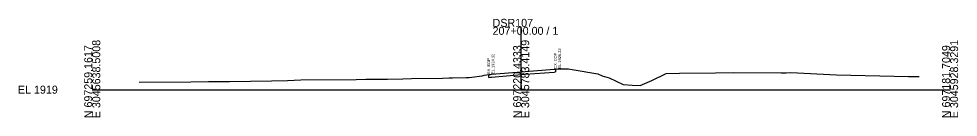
# Model space of a CAD drawing. Extents: x -26 to 19003, y -31 to 24541.
# Drawn here: x 1974.3 to 2302.8, y 17490.3 to 17524.9 of the extents above; entities that cross this region are included whole.
import ezdxf

# ---------------------------------------------------------------- set-up
doc = ezdxf.new("R2010")
doc.units = 0
for name, color, linetype in [('DESIGN - SHEET - Light Grid', 7, 'Continuous'), ('SURVEY - GROUND - Existing Pavement Layer', 7, 'Continuous'), ('SURVEY - GROUND - Existing Pavement Text', 7, 'Continuous'), ('SURVEY - GROUND - Top of Ground', 7, 'Continuous')]:
    doc.layers.add(name, color=color, linetype=linetype)

msp = doc.modelspace()

# ---------------------------------------------------------------- linework, layer by layer
at = {"layer": 'DESIGN - SHEET - Light Grid'}
for p, q in [((2150, 17500), (2150, 17522.06)), ((2000, 17500), (2150, 17500)), ((2150, 17500), (2300, 17500))]:
    msp.add_line(p, q, dxfattribs=at)
at = {"layer": 'SURVEY - GROUND - Existing Pavement Layer'}
for p, q in [((2138.64, 17504.32), (2138.64, 17505.32)), ((2138.64, 17504.32), (2139.27, 17504.37)), ((2139.27, 17504.37), (2139.67, 17504.44)), ((2139.67, 17504.44), (2150.08, 17505.29)), ((2150.08, 17505.29), (2151.45, 17505.4)), ((2151.45, 17505.4), (2161.58, 17506.2)), ((2161.58, 17506.2), (2161.96, 17506.22)), ((2161.96, 17507.22), (2161.96, 17506.22))]:
    msp.add_line(p, q, dxfattribs=at)
at = {"layer": 'SURVEY - GROUND - Top of Ground'}
msp.add_lwpolyline([(2016.43, 17502.67), (2034.47, 17502.76), (2040.6, 17502.81), (2047.94, 17502.82), (2062.64, 17503.09), (2068.24, 17503.25), (2072.93, 17503.4), (2092.35, 17503.62), (2095.63, 17503.64), (2097.21, 17503.7), (2103.23, 17503.74), (2108.58, 17503.77), (2111.64, 17503.88), (2122.43, 17504.08), (2124.78, 17504.12), (2125.33, 17504.12), (2125.96, 17504.14), (2130.78, 17504.3), (2131.29, 17504.23), (2131.76, 17504.27), (2132.76, 17504.44), (2136.4, 17504.9), (2137.06, 17505.08), (2138.64, 17505.32), (2139.27, 17505.37), (2139.67, 17505.44), (2150.08, 17506.29), (2151.45, 17506.4), (2161.58, 17507.2), (2161.96, 17507.22), (2162.87, 17507.27), (2166.17, 17507.35), (2166.52, 17507.34), (2167.89, 17507.09), (2176.77, 17505.56), (2178.37, 17504.84), (2180.73, 17504.17), (2185.65, 17501.78), (2188.81, 17501.58), (2191.65, 17501.42), (2195.66, 17503.23), (2200.71, 17505.71), (2205.36, 17505.76), (2217.92, 17505.91), (2224.1, 17506), (2240.95, 17505.87), (2242.65, 17505.9), (2244.31, 17506.02), (2260.29, 17505.16), (2285.42, 17504.67), (2289.18, 17504.6)], dxfattribs=at)

# ---------------------------------------------------------------- texts
at = {"layer": 'DESIGN - SHEET - Light Grid'}
for s, p in [('DSR107', (2140, 17522.06)), ('207+00.00 / 1', (2140, 17519.26)), ('EL 1919', (1974, 17498.6))]:
    msp.add_text(s, height=2.8, dxfattribs=at).set_placement(p)
for s, p in [('N 697259.1617', (2000, 17490)), ('E 3045638.5008', (2002.8, 17490)), ('N 697220.4333', (2150, 17490)), ('E 3045783.4149', (2152.8, 17490)), ('N 697181.7049', (2300, 17490)), ('E 3045928.3291', (2302.8, 17490))]:
    msp.add_text(s, height=2.8, rotation=90, dxfattribs=at).set_placement(p)
at = {"layer": 'SURVEY - GROUND - Existing Pavement Text'}
for s, p in [('EL.1926.22', (2163.96, 17507.42)), ('EX. EOP', (2139.14, 17505.52)), ('EL.1924.32', (2140.64, 17505.52)), ('EX. EOP', (2162.46, 17507.42))]:
    msp.add_text(s, height=1, rotation=90, dxfattribs=at).set_placement(p)

doc.saveas('drawing.dxf')
